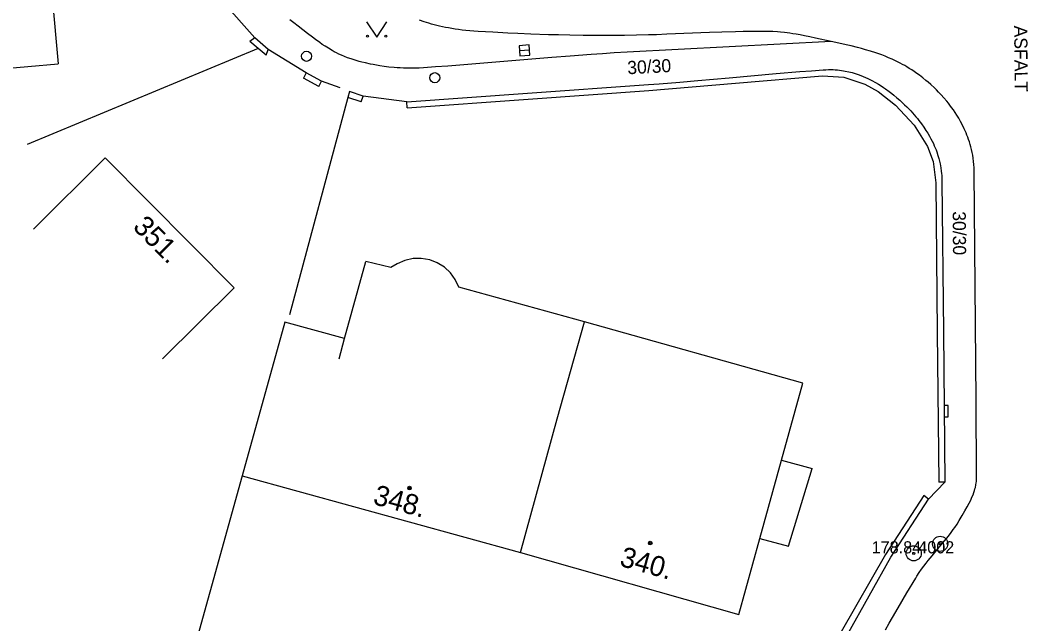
# Model space of a CAD drawing. Extents: x -538441 to -536770, y -1181008 to -1179809.
# Drawn here: x -538084.47 to -538034.52, y -1180852.71 to -1180822.81 of the extents above; entities that cross this region are included whole.
import ezdxf

# ---------------------------------------------------------------- set-up
doc = ezdxf.new("R2010")
doc.units = 0
for name, color, linetype in [('Vrstva 10', 7, 'Continuous'), ('Vrstva 11', 7, 'Continuous'), ('Vrstva 21', 7, 'Continuous'), ('Vrstva 22', 7, 'Continuous'), ('Vrstva 23', 7, 'Continuous'), ('Vrstva 24', 7, 'Continuous'), ('Vrstva 27', 7, 'Continuous'), ('Vrstva 28', 7, 'Continuous'), ('Vrstva 36', 7, 'Continuous'), ('Vrstva 39', 7, 'Continuous'), ('Vrstva 40', 7, 'Continuous'), ('Vrstva 47', 7, 'Continuous'), ('Vrstva 5', 7, 'Continuous'), ('Vrstva 7', 7, 'Continuous'), ('Vrstva 8', 7, 'Continuous')]:
    doc.layers.add(name, color=color, linetype=linetype)

msp = doc.modelspace()

# ---------------------------------------------------------------- linework, layer by layer
at = {"layer": 'Vrstva 10'}
for points in [[(-538054.973, -1180823.573), (-538055.823, -1180823.573), (-538056.566, -1180823.567), (-538057.217, -1180823.557), (-538057.786, -1180823.545), (-538058.284, -1180823.531), (-538059.155, -1180823.502), (-538059.809, -1180823.475), (-538060.299, -1180823.452), (-538061.035, -1180823.413), (-538061.77, -1180823.37), (-538061.978, -1180823.356), (-538062.178, -1180823.339), (-538062.371, -1180823.32), (-538062.557, -1180823.299), (-538062.736, -1180823.276), (-538062.908, -1180823.252), (-538063.075, -1180823.225), (-538063.235, -1180823.197), (-538063.389, -1180823.167), (-538063.538, -1180823.136), (-538063.682, -1180823.104), (-538063.821, -1180823.071), (-538063.954, -1180823.036), (-538064.083, -1180823.001), (-538064.208, -1180822.964), (-538064.448, -1180822.888), (-538064.672, -1180822.81)], [(-538045.59, -1180823.586), (-538045.812, -1180823.543), (-538046.007, -1180823.508), (-538046.178, -1180823.48), (-538046.327, -1180823.458), (-538046.589, -1180823.423), (-538046.786, -1180823.403), (-538046.934, -1180823.39), (-538047.157, -1180823.377), (-538047.38, -1180823.37), (-538047.826, -1180823.367), (-538048.245, -1180823.369), (-538048.637, -1180823.374), (-538049.005, -1180823.381), (-538049.694, -1180823.401), (-538050.297, -1180823.423), (-538052.409, -1180823.512), (-538052.936, -1180823.532), (-538053.332, -1180823.545), (-538053.926, -1180823.561), (-538054.52, -1180823.57), (-538054.973, -1180823.573)], [(-538037.582, -1180828.393), (-538037.626, -1180828.291), (-538037.671, -1180828.193), (-538037.762, -1180828.005), (-538037.855, -1180827.831), (-538037.947, -1180827.669), (-538038.038, -1180827.52), (-538038.128, -1180827.382), (-538038.215, -1180827.253), (-538038.3, -1180827.135), (-538038.383, -1180827.024), (-538038.462, -1180826.922), (-538038.539, -1180826.827), (-538038.688, -1180826.653), (-538038.823, -1180826.503), (-538038.946, -1180826.374), (-538039.056, -1180826.263), (-538039.155, -1180826.167), (-538039.332, -1180826.004), (-538039.469, -1180825.884), (-538039.574, -1180825.796), (-538039.735, -1180825.666), (-538039.9, -1180825.54), (-538040.03, -1180825.445), (-538040.157, -1180825.357), (-538040.28, -1180825.275), (-538040.4, -1180825.199), (-538040.515, -1180825.129), (-538040.628, -1180825.063), (-538040.737, -1180825.002), (-538040.844, -1180824.945), (-538041.05, -1180824.84), (-538041.244, -1180824.749), (-538041.427, -1180824.669), (-538041.599, -1180824.599), (-538041.761, -1180824.536), (-538041.914, -1180824.481), (-538042.057, -1180824.431), (-538042.327, -1180824.344), (-538042.565, -1180824.274), (-538042.774, -1180824.217), (-538042.958, -1180824.169), (-538043.282, -1180824.089), (-538043.526, -1180824.032), (-538043.896, -1180823.951), (-538044.27, -1180823.87), (-538045.045, -1180823.7), (-538045.335, -1180823.638), (-538045.59, -1180823.586)], [(-538037.15, -1180834.082), (-538037.18, -1180830.3), (-538037.184, -1180830.129), (-538037.195, -1180829.964), (-538037.21, -1180829.805), (-538037.23, -1180829.651), (-538037.253, -1180829.504), (-538037.281, -1180829.361), (-538037.311, -1180829.224), (-538037.344, -1180829.091), (-538037.38, -1180828.964), (-538037.417, -1180828.841), (-538037.457, -1180828.722), (-538037.497, -1180828.608), (-538037.539, -1180828.499), (-538037.582, -1180828.393)], [(-538037.09, -1180841.648), (-538037.12, -1180837.865), (-538037.15, -1180834.082)], [(-538037.06, -1180845.43), (-538037.09, -1180841.648)], [(-538040.515, -1180851.178), (-538040.08, -1180850.45), (-538040.021, -1180850.353), (-538039.902, -1180850.169), (-538039.786, -1180850.001), (-538039.673, -1180849.848), (-538039.565, -1180849.706), (-538039.462, -1180849.576), (-538039.264, -1180849.335), (-538038.912, -1180848.919), (-538038.65, -1180848.606), (-538038.458, -1180848.366), (-538038.318, -1180848.182), (-538038.216, -1180848.041), (-538038.142, -1180847.934), (-538038.033, -1180847.769), (-538037.93, -1180847.6), (-538037.777, -1180847.342), (-538037.642, -1180847.114), (-538037.528, -1180846.912), (-538037.432, -1180846.734), (-538037.355, -1180846.578), (-538037.292, -1180846.439), (-538037.241, -1180846.317), (-538037.201, -1180846.209), (-538037.169, -1180846.114), (-538037.145, -1180846.03), (-538037.125, -1180845.957), (-538037.097, -1180845.827), (-538037.081, -1180845.729), (-538037.071, -1180845.655), (-538037.062, -1180845.543), (-538037.06, -1180845.43)], [(-538041.573, -1180853.009), (-538041.394, -1180852.685), (-538041.234, -1180852.403), (-538040.95, -1180851.911), (-538040.515, -1180851.178)]]:
    msp.add_lwpolyline(points, dxfattribs=at)
at = {"layer": 'Vrstva 11'}
for p, q in [((-538044.27, -1180823.87), (-538049.33, -1180824.135)), ((-538049.33, -1180824.135), (-538054.39, -1180824.4)), ((-538046.734, -1180844.599), (-538045.21, -1180845.02)), ((-538046.39, -1180848.87), (-538045.21, -1180845.02)), ((-538047.807, -1180848.478), (-538046.39, -1180848.87))]:
    msp.add_line(p, q, dxfattribs=at)
for points in [[(-538063.874, -1180825.13), (-538064.47, -1180825.17), (-538064.696, -1180825.182), (-538064.908, -1180825.189), (-538065.106, -1180825.192), (-538065.292, -1180825.19), (-538065.466, -1180825.186), (-538065.629, -1180825.179), (-538065.782, -1180825.17), (-538065.925, -1180825.159), (-538066.194, -1180825.133), (-538066.429, -1180825.104), (-538066.634, -1180825.074), (-538066.814, -1180825.044), (-538066.971, -1180825.014), (-538067.109, -1180824.986), (-538067.349, -1180824.932), (-538067.53, -1180824.887), (-538067.665, -1180824.851), (-538067.867, -1180824.793), (-538068.07, -1180824.73), (-538068.24, -1180824.671), (-538068.395, -1180824.611), (-538068.537, -1180824.551), (-538068.668, -1180824.49), (-538068.788, -1180824.431), (-538068.899, -1180824.372), (-538069.002, -1180824.315), (-538069.191, -1180824.204), (-538069.353, -1180824.101), (-538069.493, -1180824.008), (-538069.615, -1180823.924), (-538069.827, -1180823.772), (-538069.984, -1180823.655), (-538070.221, -1180823.474), (-538070.46, -1180823.29), (-538070.691, -1180823.111), (-538070.903, -1180822.945), (-538071.099, -1180822.79)], [(-538054.39, -1180824.4), (-538055.021, -1180824.435), (-538055.612, -1180824.472), (-538056.166, -1180824.51), (-538057.205, -1180824.586), (-538058.113, -1180824.659), (-538061.292, -1180824.928), (-538062.086, -1180824.993), (-538063.278, -1180825.086), (-538063.874, -1180825.13)]]:
    msp.add_lwpolyline(points, dxfattribs=at)
at = {"layer": 'Vrstva 21'}
for centre, radius in [((-538038.87, -1180848.75), 0.375), ((-538040.18, -1180849.22), 0.375), ((-538038.87, -1180848.75), 0.05), ((-538040.18, -1180849.22), 0.05)]:
    msp.add_circle(centre, radius, dxfattribs=at)
at = {"layer": 'Vrstva 24'}
for p, q in [((-538038.659, -1180841.899), (-538038.66, -1180841.531)), ((-538038.476, -1180841.9), (-538038.659, -1180841.899)), ((-538038.476, -1180842.452), (-538038.476, -1180841.9)), ((-538038.66, -1180842.82), (-538038.659, -1180842.452)), ((-538038.659, -1180842.452), (-538038.476, -1180842.452))]:
    msp.add_line(p, q, dxfattribs=at)
at = {"layer": 'Vrstva 27'}
msp.add_line((-538059.221, -1180824.289), (-538059.719, -1180824.331), dxfattribs=at)
msp.add_lwpolyline([(-538059.242, -1180824.04), (-538059.74, -1180824.082), (-538059.698, -1180824.58), (-538059.2, -1180824.538)], close=True, dxfattribs=at)
at = {"layer": 'Vrstva 28'}
for centre in [(-538070.27, -1180824.6), (-538063.92, -1180825.66)]:
    msp.add_circle(centre, 0.25, dxfattribs=at)
at = {"layer": 'Vrstva 36'}
msp.add_lwpolyline([(-538067.298, -1180822.9), (-538066.798, -1180823.65), (-538066.298, -1180822.9)], dxfattribs=at)
for centre in [(-538067.248, -1180823.6), (-538066.349, -1180823.6)]:
    msp.add_circle(centre, 0.05, dxfattribs=at)
at = {"layer": 'Vrstva 39'}
for centre, radius in [((-538065.17, -1180845.99), 0.09), ((-538065.17, -1180845.99), 0.0398), ((-538053.24, -1180848.71), 0.09), ((-538053.24, -1180848.71), 0.0398)]:
    msp.add_circle(centre, radius, dxfattribs=at)
at = {"layer": 'Vrstva 5'}
for p, q in [((-538083.36, -1180816.32), (-538082.59, -1180824.97)), ((-538087.57, -1180825.413), (-538082.59, -1180824.97)), ((-538083.806, -1180833.156), (-538080.258, -1180829.633)), ((-538073.866, -1180836.069), (-538080.258, -1180829.633)), ((-538066.09, -1180835.06), (-538067.33, -1180834.76)), ((-538077.414, -1180839.592), (-538073.866, -1180836.069)), ((-538056.49, -1180837.75), (-538062.727, -1180836.03)), ((-538071.358, -1180837.764), (-538073.457, -1180845.375)), ((-538068.385, -1180838.584), (-538071.358, -1180837.764)), ((-538057.844, -1180842.563), (-538056.49, -1180837.75)), ((-538045.68, -1180840.79), (-538056.49, -1180837.75)), ((-538059.669, -1180849.178), (-538057.844, -1180842.563))]:
    msp.add_line(p, q, dxfattribs=at)
for points in [[(-538068.385, -1180838.584), (-538067.33, -1180834.76)], [(-538065.776, -1180834.875), (-538066.09, -1180835.06)], [(-538065.399, -1180834.709), (-538065.776, -1180834.875)], [(-538064.997, -1180834.619), (-538065.399, -1180834.709)], [(-538064.585, -1180834.609), (-538064.997, -1180834.619)], [(-538064.17, -1180834.68), (-538064.585, -1180834.609)], [(-538063.793, -1180834.824), (-538064.17, -1180834.68)], [(-538063.443, -1180835.041), (-538063.793, -1180834.824)], [(-538063.142, -1180835.322), (-538063.443, -1180835.041)], [(-538062.9, -1180835.656), (-538063.142, -1180835.322)], [(-538062.727, -1180836.03), (-538062.9, -1180835.656)], [(-538068.66, -1180839.58), (-538068.385, -1180838.584)], [(-538046.734, -1180844.599), (-538045.68, -1180840.79)], [(-538047.807, -1180848.478), (-538046.734, -1180844.599)], [(-538073.457, -1180845.375), (-538059.669, -1180849.178)], [(-538048.85, -1180852.25), (-538047.807, -1180848.478)], [(-538059.669, -1180849.178), (-538048.85, -1180852.25)]]:
    msp.add_lwpolyline(points, dxfattribs=at)
at = {"layer": 'Vrstva 7'}
for p, q in [((-538072.677, -1180824.209), (-538084.127, -1180828.969)), ((-538069.672, -1180826.094), (-538070.432, -1180825.684)), ((-538059.315, -1180826.425), (-538053.33, -1180826)), ((-538059.293, -1180826.724), (-538053.307, -1180826.299)), ((-538068.228, -1180826.641), (-538071.117, -1180837.399)), ((-538067.566, -1180826.864), (-538068.228, -1180826.641)), ((-538065.279, -1180827.149), (-538059.293, -1180826.724)), ((-538039.079, -1180830.865), (-538039.01, -1180838.279)), ((-538038.78, -1180830.79), (-538038.71, -1180838.24)), ((-538039.01, -1180838.279), (-538038.94, -1180845.693)), ((-538039.681, -1180846.349), (-538041.581, -1180849.282))]:
    msp.add_line(p, q, dxfattribs=at)
for points in [[(-538072.283, -1180824.542), (-538072.18, -1180824.26), (-538072.84, -1180823.69), (-538073.082, -1180823.867)], [(-538072.283, -1180824.542), (-538072.677, -1180824.209), (-538073.082, -1180823.867)], [(-538069.672, -1180826.094), (-538069.53, -1180825.83), (-538070.29, -1180825.42), (-538070.432, -1180825.684)], [(-538053.33, -1180826), (-538052.788, -1180825.96), (-538051.771, -1180825.88), (-538050.882, -1180825.805), (-538049.326, -1180825.667), (-538046.993, -1180825.458), (-538045.827, -1180825.36), (-538045.243, -1180825.314), (-538044.66, -1180825.27), (-538044.533, -1180825.263), (-538044.411, -1180825.259), (-538044.293, -1180825.259), (-538044.179, -1180825.262), (-538044.07, -1180825.268), (-538043.964, -1180825.276), (-538043.862, -1180825.286), (-538043.763, -1180825.299), (-538043.668, -1180825.313), (-538043.576, -1180825.329), (-538043.399, -1180825.366)], [(-538043.399, -1180825.366), (-538043.234, -1180825.407), (-538043.08, -1180825.452), (-538042.937, -1180825.499), (-538042.803, -1180825.548), (-538042.678, -1180825.597), (-538042.562, -1180825.647), (-538042.453, -1180825.697), (-538042.351, -1180825.746), (-538042.256, -1180825.794), (-538042.079, -1180825.891), (-538041.925, -1180825.982), (-538041.791, -1180826.067), (-538041.674, -1180826.144), (-538041.572, -1180826.215), (-538041.395, -1180826.345), (-538041.263, -1180826.447), (-538041.164, -1180826.527), (-538041.017, -1180826.651), (-538040.87, -1180826.78), (-538040.749, -1180826.891), (-538040.635, -1180827), (-538040.527, -1180827.105), (-538040.425, -1180827.209), (-538040.329, -1180827.309), (-538040.239, -1180827.408), (-538040.154, -1180827.503), (-538040.073, -1180827.597), (-538039.998, -1180827.687), (-538039.926, -1180827.776), (-538039.794, -1180827.949), (-538039.676, -1180828.113), (-538039.572, -1180828.268), (-538039.481, -1180828.415), (-538039.399, -1180828.554), (-538039.327, -1180828.686), (-538039.264, -1180828.81), (-538039.207, -1180828.927), (-538039.158, -1180829.038), (-538039.114, -1180829.142), (-538039.075, -1180829.241), (-538039.041, -1180829.334), (-538038.982, -1180829.509), (-538038.936, -1180829.664), (-538038.901, -1180829.801), (-538038.874, -1180829.922), (-538038.853, -1180830.028), (-538038.837, -1180830.122), (-538038.813, -1180830.286), (-538038.8, -1180830.411), (-538038.792, -1180830.505), (-538038.784, -1180830.647), (-538038.78, -1180830.79)], [(-538053.307, -1180826.299), (-538049.005, -1180825.939), (-538044.705, -1180825.575)], [(-538044.705, -1180825.575), (-538043.635, -1180825.638), (-538042.608, -1180825.977), (-538041.945, -1180826.349), (-538041.085, -1180827.017), (-538040.153, -1180828.006), (-538039.495, -1180829.065), (-538039.222, -1180829.813), (-538039.079, -1180830.865)], [(-538067.566, -1180826.864), (-538067.47, -1180826.58), (-538068.15, -1180826.35), (-538068.228, -1180826.641)], [(-538065.3, -1180826.85), (-538059.315, -1180826.425)], [(-538065.279, -1180827.149), (-538065.3, -1180826.85)], [(-538038.71, -1180838.24), (-538038.64, -1180845.69)], [(-538073.457, -1180845.375), (-538078.193, -1180862.363)], [(-538038.64, -1180845.69), (-538038.94, -1180845.693)], [(-538041.31, -1180849.41), (-538039.45, -1180846.54), (-538039.681, -1180846.349)], [(-538045, -1180855.66), (-538044.52, -1180853.76), (-538043.79, -1180854.01), (-538043.466, -1180853.238), (-538041.31, -1180849.41)], [(-538041.581, -1180849.282), (-538043.77, -1180853.11), (-538043.96, -1180853.64), (-538044.702, -1180853.38)]]:
    msp.add_lwpolyline(points, dxfattribs=at)
at = {"layer": 'Vrstva 8'}
for p, q in [((-538072.84, -1180823.69), (-538074.41, -1180821.92)), ((-538070.29, -1180825.42), (-538072.18, -1180824.26)), ((-538068.6, -1180826.17), (-538069.53, -1180825.83)), ((-538065.3, -1180826.85), (-538067.47, -1180826.58)), ((-538039.45, -1180846.54), (-538038.64, -1180845.69))]:
    msp.add_line(p, q, dxfattribs=at)

# ---------------------------------------------------------------- texts
at = {"layer": 'Vrstva 22'}
msp.add_text('178.84 ', height=0.6, dxfattribs=at).set_placement((-538042.264, -1180849.22))
at = {"layer": 'Vrstva 23'}
msp.add_text(' 4002', height=0.6, dxfattribs=at).set_placement((-538040.18, -1180849.22))
at = {"layer": 'Vrstva 40'}
for s, rotation, p in [('ASFALT', 270.5139, (-538035.202, -1180823.083)), ('30/30', 2.9979, (-538054.359, -1180825.491)), ('30/30', 270.4544, (-538038.249, -1180832.278))]:
    msp.add_text(s, height=0.65, rotation=rotation, dxfattribs=at).set_placement(p)
at = {"layer": 'Vrstva 47'}
for s, rotation, p in [('351.', 314.8035, (-538078.93, -1180833.097)), ('348.', 344.5825, (-538067.024, -1180846.768)), ('340.', 344.2929, (-538054.804, -1180849.826))]:
    msp.add_text(s, height=1, rotation=rotation, dxfattribs=at).set_placement(p)

doc.saveas('drawing.dxf')
